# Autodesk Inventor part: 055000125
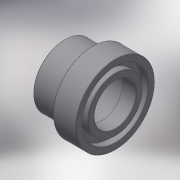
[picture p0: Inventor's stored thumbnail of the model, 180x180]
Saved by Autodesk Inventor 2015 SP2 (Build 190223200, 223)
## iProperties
Created: 2017-10
Part Number: 055000125
Material: Generic
Description: PLASSON FLANGE AD.+O-RING-CE 125
Document SubType Name: Modeling
Designer: KIM
Density: 1 g/cm^3
Appearance: Default
Author: KIM
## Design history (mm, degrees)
derived "055000.ipt"
feature "Solid1::055000.ipt"
tag "TaggingFeature1"
body "Solid1"
other parameters: "d1" = 146, "d2" = 125, "d3" = 112.5, "d4" = 17, "d5" = 69, "d6" = 169, "d8" = 5.1, "d11" = 1.25, "d12" = 5.1, "d15" = 8.475, "d_" = 125, "E_" = 146, "E_1" = 169, "l_" = 69, "B_" = 17, "d14" = 28.25
